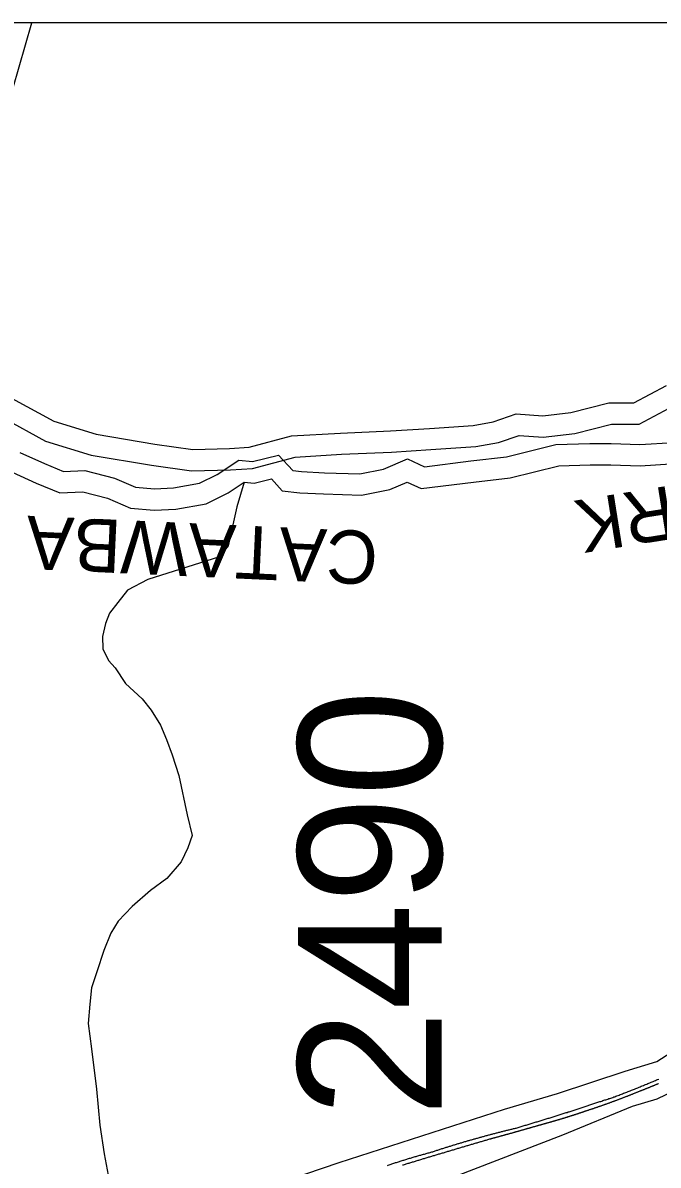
# Model space of a CAD drawing. Extents: x 1372027 to 1374286, y 553832 to 556743.
# Drawn here: x 1373305.7 to 1373346.9, y 554317.6 to 554391.5 of the extents above; entities that cross this region are included whole.
import ezdxf

# ---------------------------------------------------------------- set-up
doc = ezdxf.new("R2010")
doc.units = 0
for name, color, linetype in [('Old_Level_12', 7, 'Continuous'), ('Old_Level_44', 7, 'Continuous'), ('Prop DGN Element Guardrail', 7, 'Continuous'), ('Prop Dimension', 7, 'Continuous'), ('Prop Dimension Text', 7, 'Continuous'), ('Prop Paved Shoulder', 7, 'Continuous'), ('Prop Terminator CELL', 7, 'Continuous'), ('Sheet Sticker Incomplete CELL', 7, 'Continuous'), ('Sheet Sticker Preliminary CELL', 7, 'Continuous')]:
    doc.layers.add(name, color=color, linetype=linetype)

msp = doc.modelspace()

# ---------------------------------------------------------------- linework, layer by layer
at = {"layer": 'Old_Level_44'}
for points in [[(1373344.051, 554322.005), (1373344.122, 554322.031), (1373344.194, 554322.059), (1373344.267, 554322.085), (1373344.338, 554322.113), (1373344.41, 554322.141), (1373344.482, 554322.167), (1373344.553, 554322.192), (1373344.625, 554322.223), (1373344.696, 554322.248), (1373344.768, 554322.276), (1373344.838, 554322.307), (1373344.911, 554322.332), (1373344.981, 554322.36), (1373345.053, 554322.388), (1373345.125, 554322.416), (1373345.196, 554322.444), (1373345.268, 554322.474), (1373345.339, 554322.5), (1373345.41, 554322.528), (1373345.482, 554322.558), (1373345.553, 554322.586), (1373345.624, 554322.617), (1373345.694, 554322.645), (1373345.765, 554322.675), (1373345.836, 554322.703), (1373345.907, 554322.731), (1373345.978, 554322.761), (1373346.05, 554322.789), (1373346.121, 554322.819), (1373346.191, 554322.849), (1373346.261, 554322.879), (1373346.332, 554322.907), (1373346.403, 554322.935), (1373346.475, 554322.968), (1373346.544, 554322.996), (1373346.616, 554323.026), (1373346.687, 554323.058), (1373346.757, 554323.086), (1373346.828, 554323.118), (1373346.898, 554323.146)], [(1373346.881, 554322.849), (1373346.853, 554322.836), (1373346.824, 554322.825), (1373346.795, 554322.813), (1373346.766, 554322.8), (1373346.738, 554322.789), (1373346.709, 554322.776), (1373346.68, 554322.763), (1373346.651, 554322.752), (1373346.622, 554322.739), (1373346.594, 554322.726), (1373346.565, 554322.716), (1373346.536, 554322.703), (1373346.507, 554322.692), (1373346.478, 554322.679), (1373346.449, 554322.668), (1373346.421, 554322.655), (1373346.392, 554322.645), (1373346.363, 554322.632), (1373346.333, 554322.619), (1373346.304, 554322.608), (1373346.276, 554322.595), (1373346.247, 554322.584), (1373346.218, 554322.571), (1373346.189, 554322.561), (1373346.16, 554322.548), (1373346.131, 554322.537), (1373346.103, 554322.526), (1373346.074, 554322.513), (1373346.045, 554322.502), (1373346.016, 554322.49), (1373345.986, 554322.479), (1373345.957, 554322.466), (1373345.928, 554322.455), (1373345.9, 554322.444), (1373345.871, 554322.431), (1373345.841, 554322.421), (1373345.812, 554322.408), (1373345.783, 554322.399), (1373345.753, 554322.388), (1373345.724, 554322.375), (1373345.696, 554322.365), (1373345.667, 554322.354)], [(1373345.667, 554322.354), (1373345.632, 554322.337), (1373345.596, 554322.324), (1373345.561, 554322.309), (1373345.525, 554322.296), (1373345.489, 554322.281), (1373345.454, 554322.268), (1373345.418, 554322.251), (1373345.382, 554322.238), (1373345.346, 554322.223), (1373345.311, 554322.21), (1373345.275, 554322.192), (1373345.241, 554322.18), (1373345.205, 554322.167), (1373345.17, 554322.152), (1373345.134, 554322.139), (1373345.099, 554322.124), (1373345.062, 554322.108), (1373345.027, 554322.096), (1373344.991, 554322.08), (1373344.956, 554322.068), (1373344.92, 554322.055), (1373344.883, 554322.037), (1373344.848, 554322.025), (1373344.812, 554322.012), (1373344.777, 554321.997), (1373344.741, 554321.984), (1373344.705, 554321.971), (1373344.669, 554321.958), (1373344.634, 554321.941), (1373344.598, 554321.928), (1373344.562, 554321.915), (1373344.526, 554321.902), (1373344.49, 554321.889), (1373344.455, 554321.874), (1373344.418, 554321.861), (1373344.383, 554321.846), (1373344.348, 554321.833), (1373344.311, 554321.82), (1373344.275, 554321.807), (1373344.241, 554321.792), (1373344.203, 554321.779), (1373344.168, 554321.766), (1373344.133, 554321.753), (1373344.095, 554321.738), (1373344.061, 554321.725), (1373344.025, 554321.712), (1373343.988, 554321.699), (1373343.953, 554321.686), (1373343.916, 554321.674), (1373343.88, 554321.661), (1373343.843, 554321.648), (1373343.808, 554321.635), (1373343.772, 554321.622), (1373343.736, 554321.609), (1373343.7, 554321.594), (1373343.664, 554321.581), (1373343.628, 554321.568), (1373343.592, 554321.555), (1373343.556, 554321.542), (1373343.519, 554321.529), (1373343.484, 554321.516), (1373343.447, 554321.503), (1373343.412, 554321.491), (1373343.375, 554321.478), (1373343.34, 554321.463), (1373343.303, 554321.454), (1373343.268, 554321.441), (1373343.231, 554321.426), (1373343.195, 554321.413), (1373343.159, 554321.4), (1373343.123, 554321.387), (1373343.087, 554321.376), (1373343.05, 554321.364), (1373343.015, 554321.351), (1373342.978, 554321.338), (1373342.942, 554321.327), (1373342.906, 554321.314), (1373342.868, 554321.301), (1373342.834, 554321.288), (1373342.796, 554321.277), (1373342.759, 554321.264), (1373342.724, 554321.252), (1373342.687, 554321.241), (1373342.651, 554321.228), (1373342.615, 554321.215), (1373342.579, 554321.204), (1373342.542, 554321.191), (1373342.506, 554321.178), (1373342.47, 554321.168), (1373342.433, 554321.155), (1373342.398, 554321.144), (1373342.361, 554321.131), (1373342.323, 554321.118), (1373342.287, 554321.107), (1373342.251, 554321.094), (1373342.215, 554321.084), (1373342.178, 554321.071), (1373342.142, 554321.06), (1373342.106, 554321.047)], [(1373337.671, 554319.975), (1373337.735, 554319.994), (1373337.801, 554320.014), (1373337.866, 554320.033), (1373337.93, 554320.054), (1373337.996, 554320.072), (1373338.059, 554320.091), (1373338.124, 554320.113), (1373338.19, 554320.13), (1373338.254, 554320.151), (1373338.318, 554320.169), (1373338.383, 554320.188), (1373338.448, 554320.209), (1373338.513, 554320.227), (1373338.578, 554320.248), (1373338.643, 554320.268), (1373338.706, 554320.287), (1373338.772, 554320.306), (1373338.837, 554320.328), (1373338.901, 554320.345), (1373338.966, 554320.367), (1373339.031, 554320.384), (1373339.095, 554320.405), (1373339.16, 554320.425), (1373339.225, 554320.444), (1373339.29, 554320.464), (1373339.353, 554320.485), (1373339.418, 554320.504), (1373339.482, 554320.524), (1373339.548, 554320.545), (1373339.613, 554320.563), (1373339.676, 554320.584), (1373339.741, 554320.606), (1373339.807, 554320.623), (1373339.871, 554320.644), (1373339.936, 554320.666), (1373339.999, 554320.683), (1373340.064, 554320.705), (1373340.129, 554320.726), (1373340.194, 554320.743), (1373340.258, 554320.765), (1373340.322, 554320.787), (1373340.387, 554320.808), (1373340.451, 554320.825), (1373340.515, 554320.847), (1373340.581, 554320.868), (1373340.645, 554320.888), (1373340.71, 554320.907), (1373340.774, 554320.929), (1373340.838, 554320.95), (1373340.902, 554320.97), (1373340.967, 554320.991), (1373341.032, 554321.013), (1373341.095, 554321.03), (1373341.16, 554321.051), (1373341.225, 554321.073), (1373341.29, 554321.094), (1373341.355, 554321.114), (1373341.418, 554321.135), (1373341.483, 554321.157), (1373341.547, 554321.174), (1373341.611, 554321.196), (1373341.675, 554321.217), (1373341.74, 554321.239), (1373341.805, 554321.258), (1373341.868, 554321.28), (1373341.933, 554321.301), (1373341.997, 554321.323), (1373342.062, 554321.342), (1373342.125, 554321.364), (1373342.19, 554321.385), (1373342.255, 554321.407), (1373342.319, 554321.426), (1373342.383, 554321.447), (1373342.447, 554321.469), (1373342.512, 554321.491), (1373342.576, 554321.51), (1373342.64, 554321.531), (1373342.703, 554321.553), (1373342.768, 554321.577), (1373342.832, 554321.598), (1373342.896, 554321.618), (1373342.961, 554321.639), (1373343.025, 554321.661), (1373343.089, 554321.682), (1373343.153, 554321.702), (1373343.218, 554321.723), (1373343.283, 554321.747), (1373343.345, 554321.768), (1373343.41, 554321.79), (1373343.474, 554321.809), (1373343.538, 554321.831), (1373343.602, 554321.854), (1373343.667, 554321.876), (1373343.729, 554321.897), (1373343.794, 554321.917), (1373343.859, 554321.938), (1373343.922, 554321.962), (1373343.987, 554321.984), (1373344.051, 554322.005)], [(1373342.106, 554321.047), (1373342.079, 554321.038), (1373342.052, 554321.028), (1373342.025, 554321.019), (1373341.997, 554321.01), (1373341.971, 554321.002), (1373341.943, 554320.991), (1373341.918, 554320.982), (1373341.89, 554320.972), (1373341.864, 554320.965), (1373341.836, 554320.954), (1373341.808, 554320.946), (1373341.782, 554320.935), (1373341.754, 554320.929), (1373341.728, 554320.92), (1373341.7, 554320.909), (1373341.673, 554320.903), (1373341.646, 554320.892), (1373341.619, 554320.883), (1373341.592, 554320.875), (1373341.566, 554320.866), (1373341.538, 554320.858), (1373341.512, 554320.847), (1373341.484, 554320.838), (1373341.457, 554320.832), (1373341.43, 554320.821), (1373341.403, 554320.812), (1373341.375, 554320.804), (1373341.349, 554320.795), (1373341.321, 554320.787), (1373341.293, 554320.778), (1373341.267, 554320.767), (1373341.239, 554320.761), (1373341.212, 554320.752), (1373341.186, 554320.741), (1373341.159, 554320.735), (1373341.131, 554320.726), (1373341.105, 554320.718), (1373341.077, 554320.707), (1373341.05, 554320.7), (1373341.022, 554320.692), (1373340.996, 554320.683), (1373340.968, 554320.675), (1373340.94, 554320.666), (1373340.914, 554320.657), (1373340.886, 554320.651), (1373340.859, 554320.642), (1373340.831, 554320.631), (1373340.806, 554320.623), (1373340.778, 554320.616), (1373340.751, 554320.608), (1373340.723, 554320.599), (1373340.697, 554320.588), (1373340.669, 554320.582), (1373340.641, 554320.573), (1373340.614, 554320.567), (1373340.586, 554320.558), (1373340.56, 554320.55), (1373340.532, 554320.543), (1373340.505, 554320.532), (1373340.477, 554320.524), (1373340.451, 554320.515), (1373340.423, 554320.509), (1373340.395, 554320.5), (1373340.368, 554320.492), (1373340.34, 554320.485), (1373340.314, 554320.476), (1373340.287, 554320.468), (1373340.26, 554320.461), (1373340.232, 554320.453), (1373340.204, 554320.444), (1373340.177, 554320.436), (1373340.149, 554320.427), (1373340.123, 554320.418), (1373340.095, 554320.412), (1373340.068, 554320.403), (1373340.04, 554320.395), (1373340.012, 554320.388), (1373339.985, 554320.38), (1373339.957, 554320.371), (1373339.931, 554320.365), (1373339.903, 554320.356), (1373339.876, 554320.352), (1373339.848, 554320.343), (1373339.821, 554320.334), (1373339.794, 554320.328), (1373339.766, 554320.319), (1373339.739, 554320.311), (1373339.711, 554320.304), (1373339.683, 554320.296), (1373339.657, 554320.287), (1373339.629, 554320.281), (1373339.602, 554320.272), (1373339.574, 554320.263), (1373339.547, 554320.257), (1373339.519, 554320.25), (1373339.491, 554320.244), (1373339.464, 554320.235), (1373339.436, 554320.227), (1373339.409, 554320.22)], [(1373332.213, 554318.427), (1373332.267, 554318.442), (1373332.32, 554318.461), (1373332.375, 554318.478), (1373332.429, 554318.498), (1373332.484, 554318.515), (1373332.539, 554318.532), (1373332.593, 554318.549), (1373332.649, 554318.569), (1373332.703, 554318.586), (1373332.757, 554318.603), (1373332.811, 554318.621), (1373332.866, 554318.64), (1373332.921, 554318.655), (1373332.975, 554318.672), (1373333.03, 554318.692), (1373333.086, 554318.707), (1373333.14, 554318.726), (1373333.194, 554318.741), (1373333.249, 554318.76), (1373333.303, 554318.776), (1373333.358, 554318.795), (1373333.413, 554318.81), (1373333.467, 554318.827), (1373333.523, 554318.844), (1373333.578, 554318.862), (1373333.633, 554318.879), (1373333.686, 554318.894), (1373333.741, 554318.911), (1373333.796, 554318.928), (1373333.852, 554318.946), (1373333.907, 554318.963), (1373333.961, 554318.978), (1373334.016, 554318.993), (1373334.071, 554319.012), (1373334.126, 554319.027), (1373334.182, 554319.043), (1373334.237, 554319.06), (1373334.291, 554319.077), (1373334.346, 554319.094), (1373334.401, 554319.109), (1373334.455, 554319.124), (1373334.511, 554319.139), (1373334.566, 554319.157), (1373334.621, 554319.172), (1373334.676, 554319.187), (1373334.731, 554319.204), (1373334.787, 554319.219), (1373334.842, 554319.234), (1373334.896, 554319.251), (1373334.951, 554319.266), (1373335.006, 554319.282), (1373335.062, 554319.299), (1373335.117, 554319.314), (1373335.173, 554319.329), (1373335.228, 554319.346), (1373335.284, 554319.361), (1373335.339, 554319.376), (1373335.394, 554319.389), (1373335.449, 554319.406), (1373335.505, 554319.421), (1373335.56, 554319.437), (1373335.615, 554319.454), (1373335.671, 554319.467), (1373335.726, 554319.482), (1373335.781, 554319.497), (1373335.836, 554319.51), (1373335.891, 554319.527), (1373335.948, 554319.542), (1373336.003, 554319.555), (1373336.058, 554319.57), (1373336.113, 554319.585), (1373336.168, 554319.6), (1373336.225, 554319.615), (1373336.28, 554319.628), (1373336.335, 554319.645), (1373336.392, 554319.658), (1373336.447, 554319.671), (1373336.502, 554319.686), (1373336.556, 554319.699), (1373336.614, 554319.714), (1373336.668, 554319.729), (1373336.723, 554319.744), (1373336.78, 554319.757), (1373336.835, 554319.77), (1373336.891, 554319.785), (1373336.946, 554319.8), (1373337.002, 554319.813), (1373337.058, 554319.826), (1373337.113, 554319.841), (1373337.17, 554319.854), (1373337.225, 554319.867), (1373337.28, 554319.88), (1373337.337, 554319.893), (1373337.392, 554319.91), (1373337.448, 554319.923), (1373337.503, 554319.936), (1373337.56, 554319.949), (1373337.615, 554319.962), (1373337.671, 554319.975)], [(1373339.409, 554320.22), (1373339.375, 554320.209), (1373339.34, 554320.201), (1373339.307, 554320.19), (1373339.271, 554320.179), (1373339.237, 554320.169), (1373339.203, 554320.16), (1373339.169, 554320.151), (1373339.135, 554320.141), (1373339.099, 554320.13), (1373339.065, 554320.119), (1373339.031, 554320.113), (1373338.997, 554320.102), (1373338.963, 554320.091), (1373338.927, 554320.08), (1373338.894, 554320.072), (1373338.859, 554320.061), (1373338.825, 554320.052), (1373338.789, 554320.042), (1373338.755, 554320.033), (1373338.721, 554320.022), (1373338.687, 554320.011), (1373338.652, 554320.001), (1373338.617, 554319.994), (1373338.584, 554319.983), (1373338.549, 554319.973), (1373338.515, 554319.962), (1373338.481, 554319.953), (1373338.446, 554319.945), (1373338.411, 554319.934), (1373338.377, 554319.923), (1373338.344, 554319.915), (1373338.308, 554319.904), (1373338.274, 554319.893), (1373338.239, 554319.884), (1373338.206, 554319.876), (1373338.17, 554319.865), (1373338.136, 554319.854), (1373338.101, 554319.846), (1373338.068, 554319.837), (1373338.033, 554319.826), (1373337.998, 554319.815), (1373337.963, 554319.807), (1373337.93, 554319.796), (1373337.896, 554319.785), (1373337.86, 554319.779), (1373337.826, 554319.768), (1373337.792, 554319.757), (1373337.758, 554319.749), (1373337.722, 554319.738), (1373337.688, 554319.729), (1373337.655, 554319.721), (1373337.62, 554319.71), (1373337.585, 554319.699), (1373337.55, 554319.688), (1373337.517, 554319.682), (1373337.482, 554319.671), (1373337.447, 554319.66), (1373337.412, 554319.652), (1373337.379, 554319.641), (1373337.344, 554319.63), (1373337.309, 554319.624), (1373337.275, 554319.613), (1373337.241, 554319.602), (1373337.206, 554319.594), (1373337.171, 554319.585), (1373337.137, 554319.574), (1373337.103, 554319.566), (1373337.068, 554319.555), (1373337.033, 554319.546), (1373336.999, 554319.538), (1373336.964, 554319.527), (1373336.93, 554319.518), (1373336.896, 554319.508), (1373336.861, 554319.497), (1373336.826, 554319.49), (1373336.792, 554319.48), (1373336.758, 554319.469), (1373336.723, 554319.46), (1373336.688, 554319.449), (1373336.654, 554319.443), (1373336.62, 554319.432), (1373336.586, 554319.421), (1373336.55, 554319.413), (1373336.517, 554319.402), (1373336.482, 554319.393), (1373336.447, 554319.385), (1373336.412, 554319.374), (1373336.379, 554319.366), (1373336.343, 554319.355), (1373336.309, 554319.346), (1373336.274, 554319.338), (1373336.24, 554319.327), (1373336.206, 554319.318), (1373336.171, 554319.31), (1373336.137, 554319.299), (1373336.101, 554319.29), (1373336.068, 554319.279), (1373336.033, 554319.271), (1373335.998, 554319.262)], [(1373335.998, 554319.262), (1373335.94, 554319.245), (1373335.88, 554319.228), (1373335.822, 554319.208), (1373335.763, 554319.193), (1373335.704, 554319.174), (1373335.645, 554319.159), (1373335.587, 554319.139), (1373335.527, 554319.124), (1373335.469, 554319.107), (1373335.41, 554319.09), (1373335.351, 554319.073), (1373335.292, 554319.053), (1373335.233, 554319.038), (1373335.175, 554319.019), (1373335.116, 554319.004), (1373335.057, 554318.987), (1373334.998, 554318.969), (1373334.938, 554318.952), (1373334.88, 554318.933), (1373334.822, 554318.918), (1373334.763, 554318.898), (1373334.704, 554318.883), (1373334.645, 554318.864), (1373334.586, 554318.847), (1373334.527, 554318.832), (1373334.469, 554318.812), (1373334.41, 554318.797), (1373334.351, 554318.778), (1373334.293, 554318.76), (1373334.233, 554318.743), (1373334.174, 554318.726), (1373334.116, 554318.707), (1373334.057, 554318.692), (1373333.999, 554318.672), (1373333.939, 554318.657), (1373333.88, 554318.64), (1373333.822, 554318.621), (1373333.763, 554318.605), (1373333.705, 554318.586), (1373333.646, 554318.569), (1373333.586, 554318.552), (1373333.527, 554318.534), (1373333.469, 554318.515), (1373333.411, 554318.5), (1373333.352, 554318.481), (1373333.292, 554318.463), (1373333.233, 554318.448), (1373333.176, 554318.429), (1373333.117, 554318.412), (1373333.058, 554318.394), (1373332.999, 554318.377), (1373332.94, 554318.358), (1373332.882, 554318.341), (1373332.823, 554318.323), (1373332.764, 554318.306), (1373332.706, 554318.287), (1373332.647, 554318.272), (1373332.587, 554318.252), (1373332.529, 554318.235), (1373332.471, 554318.216), (1373332.412, 554318.201), (1373332.353, 554318.181), (1373332.293, 554318.164), (1373332.236, 554318.149), (1373332.177, 554318.13), (1373332.118, 554318.112), (1373332.059, 554318.093), (1373332.001, 554318.078), (1373331.943, 554318.059), (1373331.883, 554318.041), (1373331.825, 554318.022), (1373331.766, 554318.007), (1373331.707, 554317.988), (1373331.649, 554317.97), (1373331.59, 554317.951), (1373331.531, 554317.936), (1373331.472, 554317.917), (1373331.414, 554317.899), (1373331.356, 554317.88), (1373331.297, 554317.863), (1373331.238, 554317.845), (1373331.179, 554317.828), (1373331.12, 554317.809), (1373331.062, 554317.792), (1373331.004, 554317.772), (1373330.945, 554317.757), (1373330.885, 554317.738), (1373330.828, 554317.721), (1373330.769, 554317.701), (1373330.71, 554317.684), (1373330.652, 554317.669), (1373330.593, 554317.65), (1373330.533, 554317.63), (1373330.476, 554317.613), (1373330.417, 554317.594), (1373330.358, 554317.576), (1373330.3, 554317.561)], [(1373329.33, 554317.555), (1373329.389, 554317.576), (1373329.449, 554317.598), (1373329.508, 554317.615), (1373329.568, 554317.637), (1373329.628, 554317.654), (1373329.687, 554317.675), (1373329.746, 554317.695), (1373329.807, 554317.714), (1373329.866, 554317.733), (1373329.926, 554317.753), (1373329.985, 554317.772), (1373330.046, 554317.792), (1373330.105, 554317.809), (1373330.165, 554317.83), (1373330.224, 554317.85), (1373330.285, 554317.867), (1373330.344, 554317.886), (1373330.404, 554317.904), (1373330.464, 554317.923), (1373330.524, 554317.94), (1373330.584, 554317.96), (1373330.644, 554317.977), (1373330.703, 554317.996), (1373330.764, 554318.013), (1373330.824, 554318.033), (1373330.884, 554318.052), (1373330.945, 554318.069), (1373331.004, 554318.084), (1373331.064, 554318.104), (1373331.124, 554318.121), (1373331.185, 554318.14), (1373331.245, 554318.155), (1373331.305, 554318.175), (1373331.366, 554318.192), (1373331.426, 554318.209), (1373331.487, 554318.227), (1373331.547, 554318.244), (1373331.608, 554318.261), (1373331.668, 554318.276), (1373331.728, 554318.293), (1373331.789, 554318.311), (1373331.849, 554318.328), (1373331.909, 554318.343), (1373331.969, 554318.36), (1373332.03, 554318.377), (1373332.09, 554318.392), (1373332.15, 554318.407), (1373332.213, 554318.427)]]:
    msp.add_lwpolyline(points, dxfattribs=at)
at = {"layer": 'Prop DGN Element Guardrail'}
msp.add_lwpolyline([(1373298.735, 554366.903), (1373299.349, 554368.573), (1373299.869, 554370.175), (1373300.349, 554371.585), (1373301.785, 554376.265), (1373303.482, 554381.629), (1373305.085, 554387.264), (1373306.319, 554391.529)], dxfattribs=at)
at = {"layer": 'Prop Dimension Text'}
msp.add_lwpolyline([(1373151.666, 554391.529), (1373151.666, 554060.529), (1373482.666, 554060.529), (1373482.666, 554391.529)], close=True, dxfattribs=at)
at = {"layer": 'Prop Paved Shoulder'}
for points in [[(1373301.014, 554309.425), (1373302.952, 554310.421), (1373305.844, 554311.344), (1373311.125, 554312.813), (1373315.619, 554314.22), (1373318.881, 554315.279), (1373321.821, 554316.251), (1373326.2, 554317.745), (1373336.912, 554321.186), (1373340.336, 554322.203), (1373344.715, 554323.65), (1373346.781, 554324.285), (1373349.424, 554325.985), (1373350.401, 554326.824), (1373351.506, 554327.687), (1373353.635, 554330.214), (1373356.836, 554334.171), (1373362.701, 554340.741), (1373366.326, 554344.792), (1373371.54, 554350.942), (1373373.78, 554353.503)], [(1373347.979, 554322.434), (1373346.781, 554321.836), (1373345.184, 554321.37), (1373340.66, 554319.508), (1373333.682, 554316.823), (1373326.962, 554314.262), (1373325.903, 554313.947), (1373324.111, 554313.107), (1373320.627, 554311.324), (1373316.449, 554308.584), (1373314.931, 554307.361), (1373314.069, 554306.282), (1373313.743, 554305.4), (1373313.707, 554303.877), (1373313.76, 554302.786), (1373314, 554301.589), (1373314.499, 554299.779), (1373314.86, 554298.782), (1373314.62, 554297.079), (1373314.452, 554296.185), (1373314.461, 554295.922), (1373314.727, 554295.191), (1373315.191, 554294.112), (1373315.435, 554293.209)]]:
    msp.add_lwpolyline(points, dxfattribs=at)
at = {"layer": 'Prop Terminator CELL'}
for points in [[(1373304.449, 554365.952), (1373307.199, 554364.455), (1373310.16, 554363.545), (1373314.061, 554362.895), (1373316.653, 554362.525), (1373319.179, 554362.599), (1373320.605, 554362.678), (1373323.356, 554363.419), (1373326.362, 554363.595), (1373329.608, 554363.737), (1373332.144, 554363.898), (1373335.049, 554364.094), (1373336.527, 554364.352), (1373337.857, 554364.812), (1373339.416, 554364.699), (1373341.466, 554364.935), (1373343.848, 554365.547), (1373345.634, 554365.547), (1373348.227, 554366.929)], [(1373305.542, 554363.715), (1373307.129, 554362.994), (1373308.369, 554362.487), (1373309.75, 554362.553), (1373311.663, 554362.053), (1373313.032, 554361.466), (1373314.264, 554361.354), (1373315.486, 554361.415), (1373317.171, 554361.716), (1373318.322, 554362.291), (1373319.722, 554363.224), (1373320.607, 554363.125), (1373322.291, 554363.546), (1373323.205, 554362.541), (1373323.77, 554362.471), (1373325.25, 554362.403), (1373327.547, 554362.338), (1373329.074, 554362.631), (1373330.625, 554363.309), (1373331.743, 554362.794), (1373334.731, 554363.167), (1373337.04, 554363.438), (1373340.229, 554364.224), (1373342.434, 554364.3), (1373343.819, 554364.3), (1373345.674, 554364.232), (1373347.854, 554364.364)]]:
    msp.add_lwpolyline(points, dxfattribs=at)
at = {"layer": 'Sheet Sticker Incomplete CELL'}
for points in [[(1373305.004, 554367.219), (1373307.736, 554365.731), (1373310.477, 554364.889), (1373314.271, 554364.257), (1373316.731, 554363.906), (1373319.12, 554363.976), (1373320.385, 554364.046), (1373323.134, 554364.786), (1373326.292, 554364.971), (1373329.534, 554365.113), (1373332.054, 554365.273), (1373334.884, 554365.464), (1373336.181, 554365.69), (1373337.674, 554366.207), (1373339.387, 554366.083), (1373341.214, 554366.293), (1373343.674, 554366.925), (1373345.29, 554366.925), (1373347.398, 554368.049)], [(1373305.004, 554367.219), (1373307.736, 554365.731), (1373310.477, 554364.889), (1373314.271, 554364.257), (1373316.731, 554363.906), (1373319.12, 554363.976), (1373320.385, 554364.046), (1373323.134, 554364.786), (1373326.292, 554364.971), (1373329.534, 554365.113), (1373332.054, 554365.273), (1373334.884, 554365.464), (1373336.181, 554365.69), (1373337.674, 554366.207), (1373339.387, 554366.083), (1373341.214, 554366.293), (1373343.674, 554366.925), (1373345.29, 554366.925), (1373347.398, 554368.049)], [(1373305.037, 554362.431), (1373306.583, 554361.729), (1373308.129, 554361.097), (1373309.605, 554361.167), (1373311.214, 554360.745), (1373312.69, 554360.113), (1373314.236, 554359.973), (1373315.642, 554360.043), (1373317.609, 554360.394), (1373319.015, 554361.097), (1373320.069, 554361.799), (1373320.701, 554361.729), (1373321.826, 554362.01), (1373322.528, 554361.237), (1373323.653, 554361.097), (1373325.199, 554361.026), (1373327.658, 554360.956), (1373329.486, 554361.307), (1373330.61, 554361.799), (1373331.523, 554361.377), (1373334.897, 554361.799), (1373337.286, 554362.08), (1373340.42, 554362.852), (1373342.458, 554362.922), (1373343.793, 554362.922), (1373345.691, 554362.852), (1373348.01, 554362.993)], [(1373305.037, 554362.431), (1373306.583, 554361.729), (1373308.129, 554361.097), (1373309.605, 554361.167), (1373311.214, 554360.745), (1373312.69, 554360.113), (1373314.236, 554359.973), (1373315.642, 554360.043), (1373317.609, 554360.394), (1373319.015, 554361.097), (1373320.069, 554361.799), (1373320.701, 554361.729), (1373321.826, 554362.01), (1373322.528, 554361.237), (1373323.653, 554361.097), (1373325.199, 554361.026), (1373327.658, 554360.956), (1373329.486, 554361.307), (1373330.61, 554361.799), (1373331.523, 554361.377), (1373334.897, 554361.799), (1373337.286, 554362.08), (1373340.42, 554362.852), (1373342.458, 554362.922), (1373343.793, 554362.922), (1373345.691, 554362.852), (1373348.01, 554362.993)]]:
    msp.add_lwpolyline(points, dxfattribs=at)
at = {"layer": 'Sheet Sticker Preliminary CELL'}
msp.add_lwpolyline([(1373320.069, 554361.799), (1373319.583, 554360.195), (1373319.021, 554357.667), (1373318.459, 554356.965), (1373313.82, 554355.49), (1373312.508, 554354.794), (1373311.872, 554354.01), (1373311.341, 554353.306), (1373311.086, 554352.639), (1373310.896, 554351.803), (1373310.915, 554351.005), (1373311.279, 554350.24), (1373311.701, 554349.769), (1373312.386, 554348.746), (1373313.452, 554347.758), (1373314.04, 554347.03), (1373314.641, 554346.055), (1373315.036, 554345.12), (1373315.395, 554344.145), (1373315.833, 554342.793), (1373316.368, 554340.261), (1373316.686, 554338.909), (1373316.412, 554338.116), (1373315.98, 554337.201), (1373315.062, 554336.127), (1373313.995, 554335.35), (1373312.802, 554334.325), (1373311.904, 554333.375), (1373311.423, 554332.589), (1373310.97, 554331.463), (1373310.528, 554330.088), (1373310.181, 554329.043), (1373310.073, 554327.995), (1373309.961, 554326.735), (1373310.17, 554325.095), (1373310.496, 554322.481), (1373310.708, 554320.166), (1373310.998, 554318.313), (1373311.262, 554316.92)], dxfattribs=at)

# ---------------------------------------------------------------- texts
at = {"layer": 'Old_Level_12'}
msp.add_text('2490', height=9.3012, rotation=90, dxfattribs=at).set_placement((1373332.837, 554320.691))
at = {"layer": 'Prop Dimension'}
for s, rotation, p in [('SOUTH FORK', 189.04387, (1373371.153, 554365.321)), ('CATAWBA', 177.39924, (1373328.787, 554358.585))]:
    msp.add_text(s, height=3.4449, rotation=rotation, dxfattribs=at).set_placement(p)

doc.saveas('drawing.dxf')
